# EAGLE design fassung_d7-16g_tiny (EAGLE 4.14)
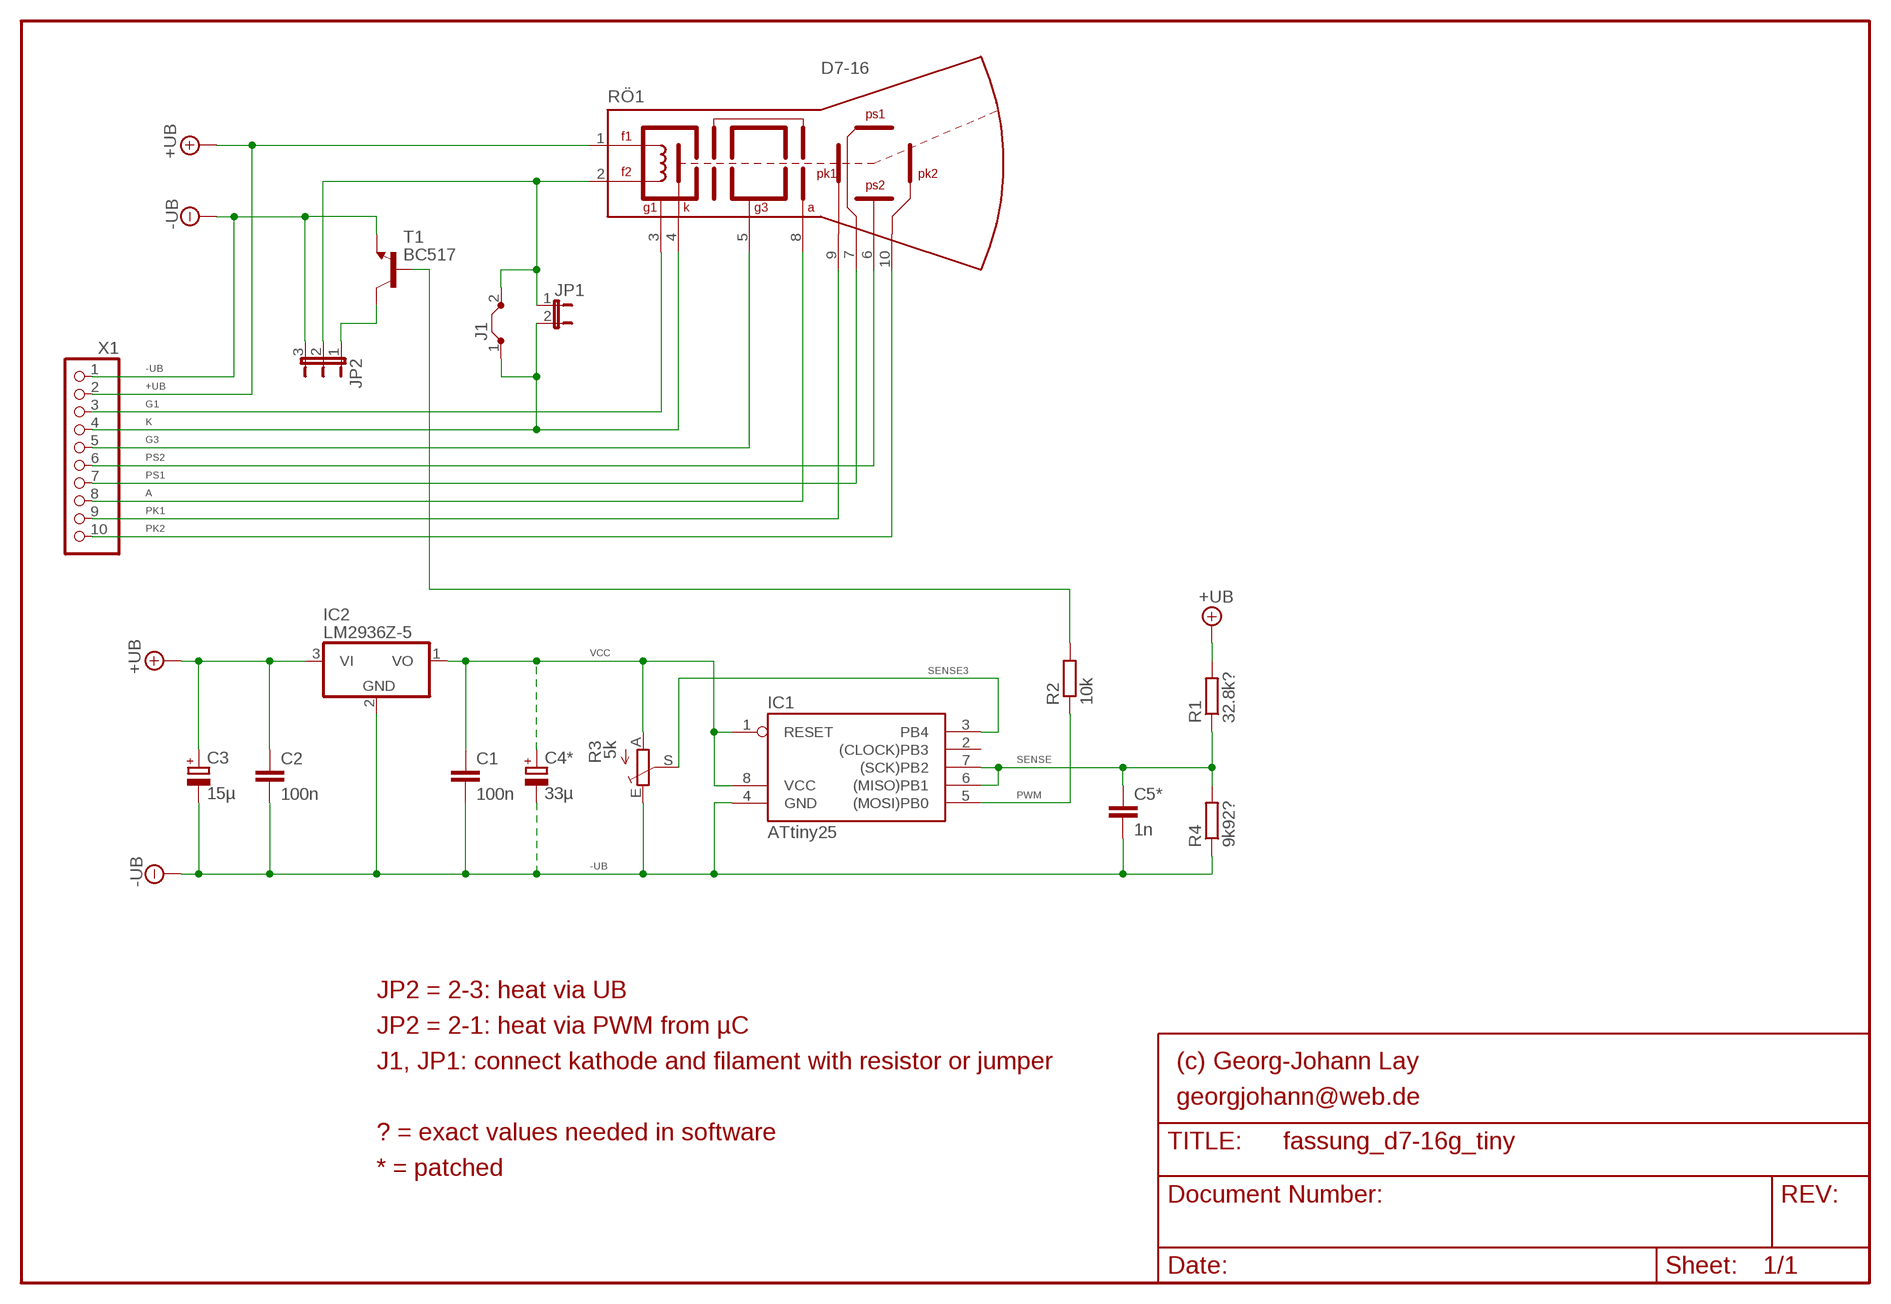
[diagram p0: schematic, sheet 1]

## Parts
C1  100n  C-EU050-024X044  [C050-024X044]
C2  100n  C-EU050-024X044  [C050-024X044]
C3  15µ  CPOL-EUE2.5-6  [E2,5-6]
C4*  33µ  CPOL-EUE2.5-6  [E2,5-6]
C5*  1n  C-EU025-024X044  [C025-024X044]
IC1  ATtiny25  TINY22P  [DIL08]
IC2  LM2936Z-5  78L05Z  [TO92]
J1  J7MM  [07]
JP1  JP1E  [JP1]
JP2  JP2E  [JP2]
R1  32.8k?  R-EU_0204/2V  [0204V]
R2  10k  R-EU_0204/2V  [0204V]
R3  5k  TRIM_EU-S75H  [S75H]
R4  9k92?  R-EU_0204/2V  [0204V]
RÖ1  D7-16  [D7-16]
T1  BC517  BC548-  [TO92-]
X1  PINHD-1X10  [1X10]

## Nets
+UB: C2.1 C3.+ IC2.3(VI) R1.2 RÖ1.1(F1) X1.2
-UB: C1.2 C2.2 C3.- C4*.- C5*.2 IC1.4(GND) IC2.2(GND) JP2.3 R3.E R4.1 T1.1(E) X1.1
A: RÖ1.8(A) X1.8
F2: J1.2 JP1.1 JP2.2 RÖ1.2(F2)
G1: RÖ1.3(G1) X1.3
G3: RÖ1.5(G3) X1.5
K: J1.1 JP1.2 RÖ1.4(K) X1.4
PK1: RÖ1.9(PK1) X1.9
PK2: RÖ1.10(PK2) X1.10
PS1: RÖ1.7(PS1) X1.7
PS2: RÖ1.6(PS2) X1.6
PWM: IC1.5((MOSI)PB0) R2.1
SENSE: C5*.1 IC1.6((MISO)PB1) IC1.7((SCK)PB2) R1.1 R4.2
SENSE3: IC1.3(PB4) R3.S
T1.B: R2.2 T1.2(B)
T1.C: JP2.1 T1.3(C)
VCC: C1.1 C4*.+ IC1.1(RESET) IC1.8(VCC) IC2.1(VO) R3.A
Unconnected: IC1.2((CLOCK)PB3)

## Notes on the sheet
- JP2 = 2-3: heat via UB
- JP2 = 2-1: heat via PWM from µC
- J1, JP1: connect kathode and filament with resistor or jumper | (c) Georg-Johann Lay
- georgjohann@web.de
- ? = exact values needed in software
- * = patched

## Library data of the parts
C1 C2 C5* = rcl:C-EU: CAPACITOR, European symbol
C3 C4* = rcl:CPOL-EU: POLARIZED CAPACITOR, European symbol
IC1 = atmel:TINY22: MICROCONTROLLER 1K ROM 128 bytes RAM 128 bytes EEPROM
IC2 = linear:78*: Positive VOLTAGE REGULATOR Source: http://cache.national.com/ds/LM/LM78L05.pdf http://www.fairchildsemi.com/ds/LM/LM7805.pdf
J1 = jumper:J: Bridge
JP1 = jumper:JP1E: JUMPER
JP2 = jumper:JP2E: JUMPER
R1 R2 R4 = rcl:R-EU_: RESISTOR, European symbol
R3 = pot:TRIM_EU-: POTENTIOMETER
RÖ1 = eigene:D7-16: Kathodenstrahlröhre D7-16G, Rückansicht
T1 = eigene:BC548*
X1 = pinhead:PINHD-1X10: PIN HEADER

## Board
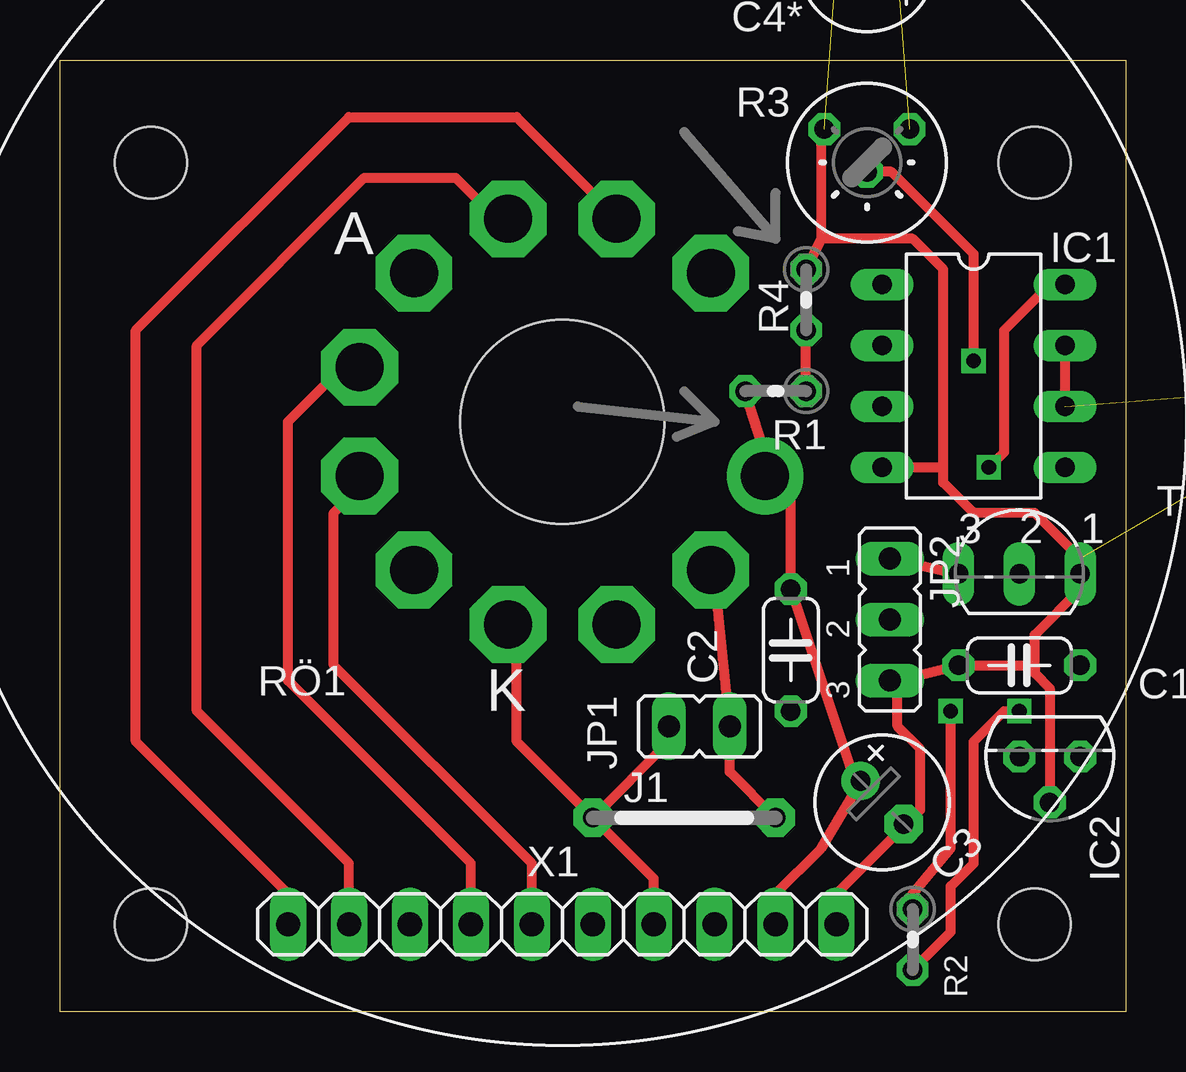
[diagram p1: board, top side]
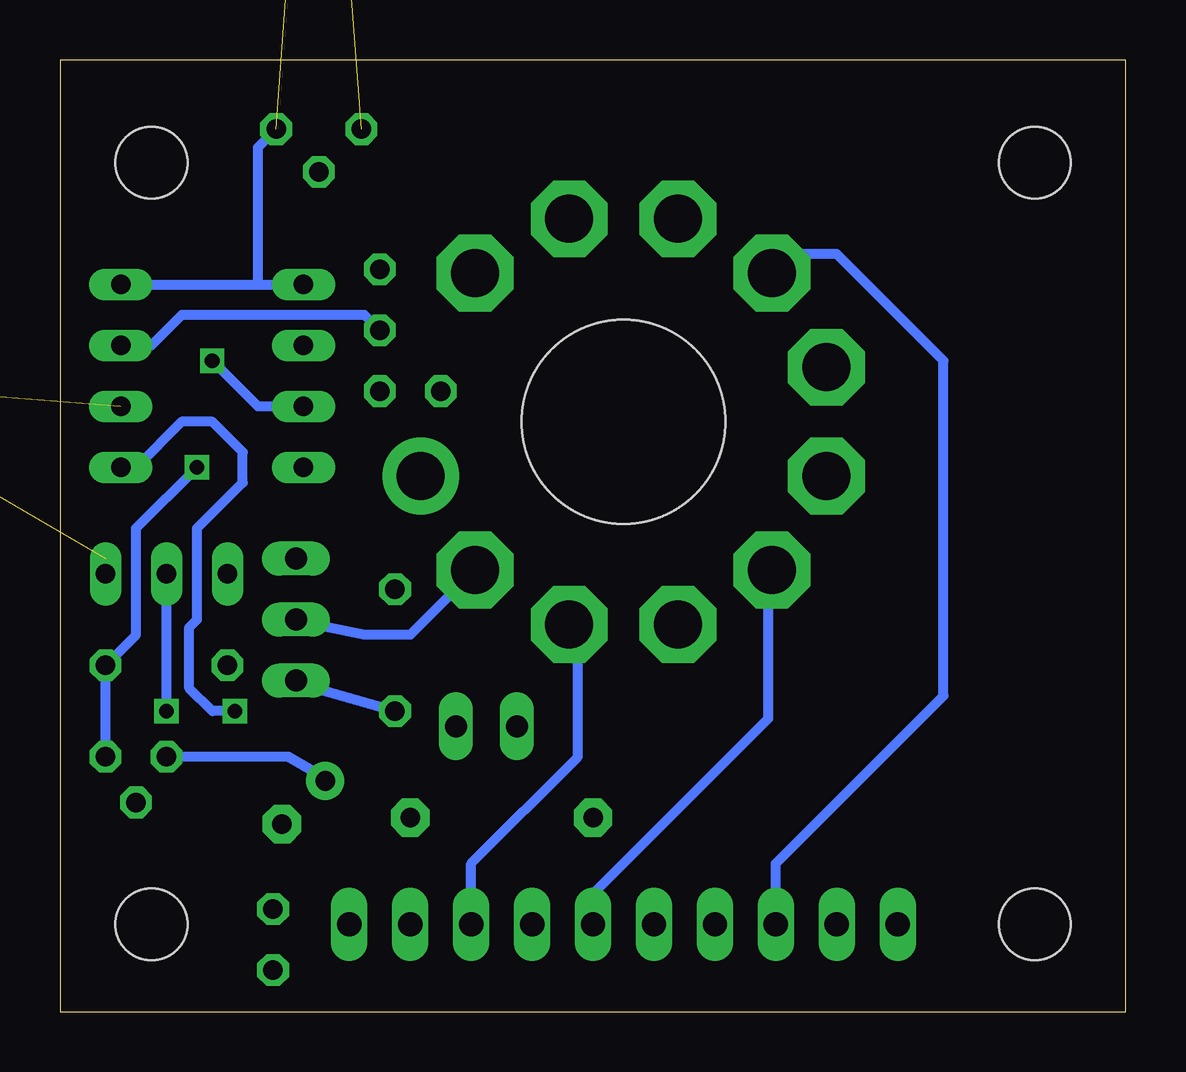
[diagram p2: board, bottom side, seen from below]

Size 44.43 x 39.68 mm. Coordinates in mm from the lower left corner, seen from the top.
Outline: 44.43,0 0,0 0,39.68 44.43,39.68 44.43,0
Copper layers (1+16): Top 0.035mm / dielectric 1.5mm / Bottom 0.035mm
Design rules "default": minimum track width 10mil, minimum drill 24mil, track to track 8mil, track to pad 8mil, pad to pad 8mil, via to via 8mil, smd to smd 8mil, copper to edge 40mil, drill to drill 8mil, minimum pad ring 10mil, minimum via ring 8mil, stop-mask expansion 4mil, vias tented up to drill 0mil, thermal gap 10mil

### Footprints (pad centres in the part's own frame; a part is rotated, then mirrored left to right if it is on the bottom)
C050-024X044 = drill 0.813 octagon: 1 -2.54,0; 2 2.54,0
E2,5-6 = drill 0.813 pad 1.6 round: + -1.27,0 | drill 0.813 pad 1.6 octagon: - 1.27,0
C025-024X044 = drill 0.813 octagon: 1 -1.27,0; 2 1.27,0
DIL08 = drill 0.813 long: 1 -3.81,-3.81; 2 -1.27,-3.81; 3 1.27,-3.81; 4 3.81,-3.81; 5 3.81,3.81; 6 1.27,3.81; 7 -1.27,3.81; 8 -3.81,3.81
TO92 = drill 0.813 octagon: 1 -1.27,0; 2 0,1.905; 3 1.27,0
07 = drill 0.813 pad 1.6 octagon: 1 -3.81,0; 2 3.81,0
JP1 = drill 0.914 long: 1 0,-1.27; 2 0,1.27
JP2 = drill 0.914 long: 1 -2.54,0; 2 0,0; 3 2.54,0
0204V = drill 0.813 octagon: 1 -1.27,0; 2 1.27,0
S75H = drill 0.813 octagon: A -1.778,-1.397; E 1.778,-1.397; S 0,0.381
D7-16 = drill 2 pad 3.2 round: 1 8.452,-2.265 | drill 2 pad 3.2 octagon: 2 6.187,-6.187; 3 2.265,-8.452; 4 -2.265,-8.452; 5 -6.187,-6.187; 6 -8.452,-2.265; 7 -8.452,2.265; 8 -6.187,6.187; 9 -2.265,8.452; 10 2.265,8.452; 11 6.187,6.187 | hole 8.5: 0,0
TO92- = drill 0.813 long: 1 2.54,-1.27; 2 0,-1.27; 3 -2.54,-1.27
BOHRUNG_3MM = hole 3: 0,0
1X10 = drill 1.016 long: 1 -11.43,0; 2 -8.89,0; 3 -6.35,0; 4 -3.81,0; 5 -1.27,0; 6 1.27,0; 7 3.81,0; 8 6.35,0; 9 8.89,0; 10 11.43,0

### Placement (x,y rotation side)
C1  39.99,14.44 180 top
C2  30.46,15.08 270 top
C3  34.27,8.73 315 top
C4*  not placed on the board
C5*  not placed on the board
IC1  38.08,26.51 270 top
IC2  41.26,10.63 180 top
J1  26.02,8.09 0 top
JP1  26.66,11.9 90 top
JP2  34.59,16.35 270 top
R1  29.83,25.87 180 top
R2  35.55,3.01 270 top
R3  33.64,35.4 180 top
R4  31.1,29.68 270 top
RÖ1  20.94,24.6 0 top
T1  39.99,19.52 0 top
U$1  [BOHRUNG_3MM]  40.62,35.4 0 bottom
U$2  [BOHRUNG_3MM]  3.79,35.4 0 bottom
U$3  [BOHRUNG_3MM]  40.62,3.65 0 bottom
U$4  [BOHRUNG_3MM]  3.79,3.65 0 bottom
X1  20.94,3.65 180 top

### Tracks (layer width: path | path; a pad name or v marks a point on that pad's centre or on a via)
+UB
  Top 0.406: X1.2 29.83,4.92 31.73,6.82 33.64,10 C3.+ | 29.39,22.5 RÖ1.1 | C3.+ | 29.39,22.5 29.63,22.5 R1.2 | 29.39,22.5 30.46,21.43 C2.1 33,10 C3.+
  Bottom 0.406: IC2.3 34.91,10.63 33.38,9.73 C3.+
-UB  (2 unrouted)
  Top 0.406: X1.1 32.37,4.92 35.28,7.83 | 34.91,13.81 34.91,11.9 35.86,10.95 35.86,8.41 35.28,7.83 | 35.28,7.83 C3.- | 36.81,22.7 36.81,30.95 35.55,32.22 31.73,32.22 | R3.E 31.73,36.66 31.73,32.22 | 36.81,22.7 36.81,22.06 38.08,20.79 40.62,20.79 42.53,18.89 T1.1 42.53,17.62 40.62,15.71 40.62,14.44 | 36.81,22.7 IC1.4 | 34.91,13.81 C1.2 40.62,14.44 | 34.91,13.81 JP2.3 | 31.73,32.22 R4.1 | IC2.2 41.26,13.49 40.62,14.12 40.62,14.44
  Bottom 0.406: C2.2 34.91,13.81 JP2.3
A
  Bottom 0.406: X1.8 14.59,6.18 7.61,13.17 7.61,27.14 12.05,31.59 13.96,31.59 RÖ1.8 14.91,30.63
F2
  Top 0.406: RÖ1.2 27.29,18.25 JP1.1 27.93,10 J1.2
  Bottom 0.406: JP2.2 34.91,16.35 31.73,15.71 29.83,15.71 RÖ1.2
G1
  Bottom 0.406: RÖ1.3 23.21,16.07 22.84,15.71 22.84,10.63 27.29,6.18 X1.3
G3
  Bottom 0.406: RÖ1.5 14.91,18.25 14.91,12.22 22.21,4.92 X1.5
K
  Top 0.406: RÖ1.4 18.6,16.15 19.04,15.71 19.04,11.27 J1.1 | JP1.2 25.39,11.27 J1.1 | J1.1 24.75,5.55 X1.4
PK1
  Top 0.406: X1.9 12.05,6.18 5.7,12.54 5.7,27.78 12.69,34.76 16.5,34.76 18.4,32.86 18.6,33.05 RÖ1.9
PK2
  Top 0.406: X1.10 9.51,4.92 3.16,11.27 3.16,28.41 12.05,37.3 19.04,37.3 23.21,33.13 RÖ1.10
PS1
  Top 0.406: X1.7 17.13,6.18 9.51,13.81 9.51,24.6 12.05,27.14 12.37,27.14 12.64,26.87 | 12.64,26.87 12.69,26.82 | 12.64,26.87 RÖ1.7
PS2
  Top 0.406: X1.6 19.67,6.18 11.42,14.44 11.42,20.79 12.69,22.06 12.49,22.26 RÖ1.6
PWM  (via drill 0.61)
  Top 0.406: R2.1 35.55,4.92 37.13,6.82 v37.13,12.54
  Bottom 0.406: IC1.5 41.26,22.7 39.36,24.6 38.08,24.6 36.81,23.33 36.81,22.06 38.72,20.16 38.72,16.35 39.04,16.03 39.04,13.49 38.08,12.54 v37.13,12.54
SENSE  (1 unrouted)
  Top 0.406: R1.1 R4.2 | IC1.7 IC1.6
  Bottom 0.406: IC1.7 40.62,27.78 39.36,29.05 31.73,29.05 R4.2
SENSE3  (via drill 0.61)
  Top 0.406: R3.S 34.66,35.01 38.08,31.59 v38.08,27.14
  Bottom 0.406: v38.08,27.14 36.18,25.23 IC1.3
T1.B  (via drill 0.61)
  Top 0.406: v39.99,12.54 39.36,12.54 38.08,11.27 38.08,6.18 37.13,5.23 37.13,3.33 R2.2
  Bottom 0.406: v39.99,12.54 T1.2
T1.C
  Top 0.406: JP2.1 T1.3
VCC  (via drill 0.61)  (1 unrouted)
  Top 0.406: v38.72,22.7 39.36,23.33 39.36,28.41 41.26,30.32 IC1.8
  Bottom 0.406: IC1.8 36.18,30.32 | 36.18,30.32 IC1.1 | R3.A 36.18,36.03 36.18,30.32 | v38.72,22.7 41.26,20.16 41.26,15.71 C1.1 IC2.1

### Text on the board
tDocu: -Ub | +Ub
